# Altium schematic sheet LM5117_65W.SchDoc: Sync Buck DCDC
size 431 x 279 mm; Engineer: Yutao Wang (Steven); Organization: TESLA Motors, INC; Address1: 3500 Deer Creek Road; Address2: Palo Alto, CA; Address4: U.S.A.; SheetNumber: 6; SheetTotal: 7
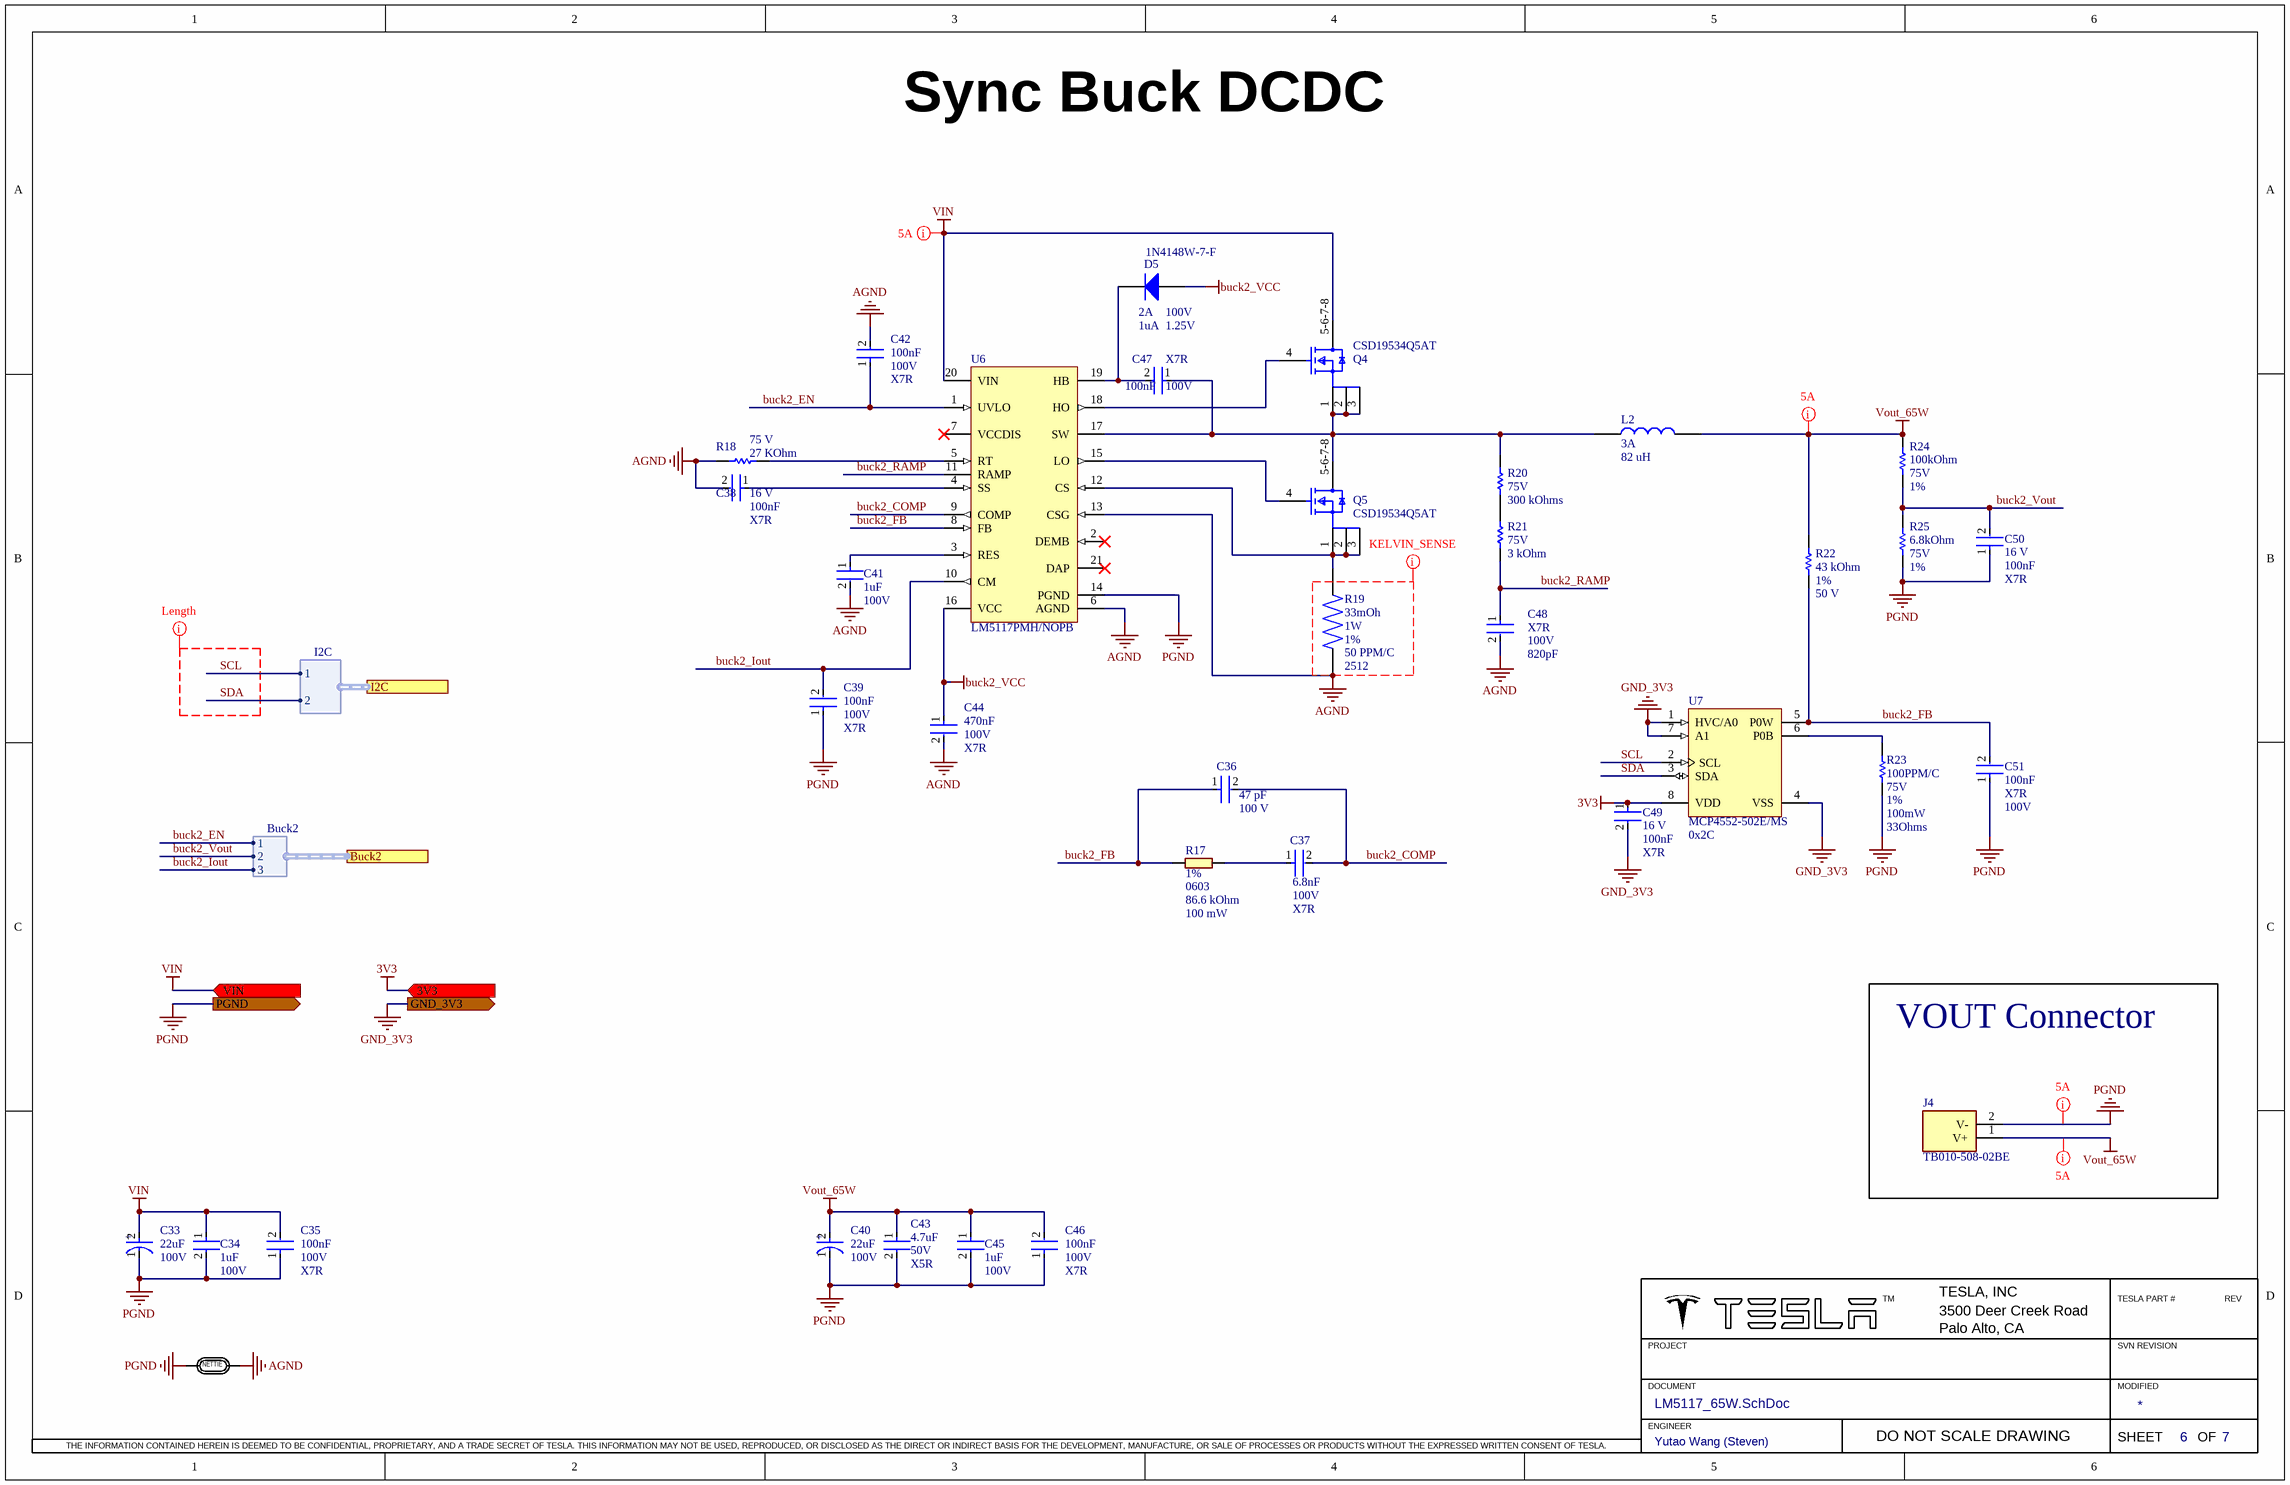
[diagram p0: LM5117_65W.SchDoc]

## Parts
C33  Capacitance: 22uF  Voltage Rating (DC): 100V  [FP-TGF-MFG]  (hidden comment: EEE-TG2A220UP)
C34  Capacitance: 1uF  Voltage: 100V  [FP-C2012-125-0_2-IPC_A]  (hidden comment: C2012X7S2A105K125AB)
C35  Capacitance: 100nF  Dielectric: X7R  Voltage Rating (DC): 100V  [FP-CC1206-0_3-1_45-IPC_C]  (hidden comment: CC1206KKX7R0BB104)
C36  Capacitance: 47 pF  Voltage Rating: 100 V  [FP-C0603C-CF-MFG]  (hidden comment: C0603C470J1GACTU)
C37  Voltage Rating: 100V  Capacitance: 6.8nF  Dielectric: X7R  [FP-GCM188-0_1-IPC_C]  (hidden comment: GCM188R72A682KA37D)
C38  Voltage Rating: 16 V  Capacitance: 100nF  Temperature Characteristic: X7R  [FP-C0402-BB-MFG]  (hidden comment: C0402C104K4RACTU)
C39  Capacitance: 100nF  Dielectric: X7R  Voltage Rating (DC): 100V  [FP-CC1206-0_3-1_45-IPC_C]  (hidden comment: CC1206KKX7R0BB104)
C40  Capacitance: 22uF  Voltage Rating (DC): 100V  [FP-TGF-MFG]  (hidden comment: EEE-TG2A220UP)
C41  Capacitance: 1uF  Voltage: 100V  [FP-C2012-125-0_2-IPC_A]  (hidden comment: C2012X7S2A105K125AB)
C42  Capacitance: 100nF  Dielectric: X7R  Voltage Rating (DC): 100V  [FP-CC1206-0_3-1_45-IPC_C]  (hidden comment: CC1206KKX7R0BB104)
C43  Voltage Rating (DC): 50V  Capacitance: 4.7uF  Dielectric: X5R  [FP-GRM21B-0_15-IPC_C]  (hidden comment: GRM21BR61H475ME51L)
C44  Capacitance: 470nF  Voltage Rating (DC): 100V  Dielectric: X7R  [FP-GRM21B-0_15-IPC_A]  (hidden comment: GRM21BR72A474MA73L)
C45  Capacitance: 1uF  Voltage: 100V  [FP-C2012-125-0_2-IPC_A]  (hidden comment: C2012X7S2A105K125AB)
C46  Capacitance: 100nF  Dielectric: X7R  Voltage Rating (DC): 100V  [FP-CC1206-0_3-1_45-IPC_C]  (hidden comment: CC1206KKX7R0BB104)
C47  Capacitance: 100nF  Dielectric: X7R  Voltage Rating (DC): 100V  [FP-CC1206-0_3-1_45-IPC_C]  (hidden comment: CC1206KKX7R0BB104)
C48  Capacitance: 820pF  Voltage: 100V  Grade: X7R  [FP-GCM155-0_05-IPC_A]  (hidden comment: GCM155R72A821KA37J)
C49  Voltage Rating: 16 V  Capacitance: 100nF  Temperature Characteristic: X7R  [FP-C0402-BB-MFG]  (hidden comment: C0402C104K4RACTU)
C50  Voltage Rating: 16 V  Capacitance: 100nF  Temperature Characteristic: X7R  [FP-C0402-BB-MFG]  (hidden comment: C0402C104K4RACTU)
C51  Capacitance: 100nF  Dielectric: X7R  Voltage Rating (DC): 100V  [FP-CC1206-0_3-1_45-IPC_C]  (hidden comment: CC1206KKX7R0BB104)
D5  1N4148W-7-F  Max Surge Current: 2A  Peak Reverse Voltage: 100V  Ir - Reverse Current: 1uA  Vf - Forward Voltage: 1.25V  [DIOD-SOD123-2_V]
J4  TB010-508-02BE  [CUI_TB010-508-02BE]
L2  Max DC Current: 3A  Inductance: 82 uH  [IHLP5050EZER820M5A]  (hidden comment: IHLP5050EZER820M5A)
NT4  BOARD FEATURE  [NETTIE-0.5X0.5X0.4]  (value not drawn)  (net tie, no BOM)
Q4  CSD19534Q5AT  [FP-DQJ0008A-MFG]
Q5  CSD19534Q5AT  [FP-DQJ0008A-MFG]
R17  value 86.6 kOhm  Tolerence: 1%  Size: 0603  Power: 100 mW  [PE1206FRM470R02L]  (hidden comment: RC0603FR-0786K6L)
R18  Resistance: 27 KOhm  Voltage: 75 V  [RESC1608X55X25LL10T15]  (hidden comment: RC0603FR-0715KL)
R19  value 33mOh  Power: 1W  Tolerence: 1%  PPM: 50 PPM/C  Size: 2512  [PE2512FKE070R033L]  (hidden comment: PE2512FKE070R033L)
R20  Voltage: 75V  Resistance: 300 kOhms  [RESC1608X55X25ML10T15]  (hidden comment: RC0603FR-10300KL)
R21  Voltage: 75V  Resistance: 3 kOhm  [RESC1608X55X25ML10T15]  (hidden comment: RC0603FR-103KL)
R22  Resistance: 43 kOhm  Tolerence: 1%  Voltage: 50 V  [RESC1005X40X25NL05T10]  (hidden comment: RC0402FR-0743KL)
R23  Temperature Coefficient: 100PPM/C  Voltage Rating: 75V  Tolerance: 1%  Power Rating: 100mW  Resistance: 33Ohms  [RESC1608X55X25LL10T15]  (hidden comment: RC0603FR-0733RL)
R24  Resistance: 100kOhm  Voltage: 75V  Tolerence: 1%  [RESC1608X55X30ML15T15]  (hidden comment: ERJ-3EKF1003V)
R25  Voltage: 75V  Resistance: 6.8kOhm  Tolerence: 1%  [RESC1609X55X30NL15T15]  (hidden comment: ERJ-3EKF6801V)
U6  LM5117PMH/NOPB  [PWP0020A_N]
U7  MCP4552-502E/MS  [MSOP-MS8_N]

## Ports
3V3 (in), Buck2 (harness Buck2), GND_3V3 (out), I2C (harness I2C), PGND (out), VIN (in)

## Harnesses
I2C: 1, 2
Buck2: 1, 3, 2

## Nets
3V3: C49.1 U7.8(VDD) ; port 3V3
AGND: C38.2 C41.2 C42.2 C44.2 C48.2 NT4.1(C1) R18.1 R19.1 U6.6(AGND) U6.13(CSG)
buck2_VCC: C44.1 D5.1(A) U6.16(VCC)
GND_3V3: C49.2 U7.1(HVC/A0) U7.4(VSS) U7.7(A1) ; port GND_3V3
PGND: C33.1(C) C34.2 C35.1 C39.1 C40.1(C) C43.2 C45.2 C46.1 C50.1 C51.1 J4.2(V-) NT4.2(C2) R23.2 R25.1 U6.14(PGND) ; port PGND
VIN: C33.2(A) C34.1 C35.2 Q4.5-6-7-8(D) U6.20(VIN) ; port VIN
Vout_65W: C40.2(A) C43.1 C45.1 C46.2 J4.1(V+) L2.2 R22.2 R24.2
buck2_COMP: C36.2 C37.2 U6.9(COMP)
buck2_EN: C42.1 U6.1(UVLO) ; port Buck2.1
buck2_FB: C36.1 C51.2 R17.1 R22.1 U6.8(FB) U7.5(P0W)
buck2_Iout: C39.2 U6.10(CM) ; port Buck2.3
buck2_RAMP: C48.1 R21.1 U6.11(RAMP)
buck2_Vout: C50.2 R24.1 R25.2 ; port Buck2.2
SCL: U7.2(SCL) ; port I2C.1
SDA: U7.3(SDA) ; port I2C.2
NetC37_1: C37.1 R17.2
NetC38_1: C38.1 U6.4(SS)
NetC41_1: C41.1 U6.3(RES)
NetC47_1: C47.1 L2.1 Q4.1(S) Q4.2(S) Q4.3(S) Q5.5-6-7-8(D) R20.2 U6.17(SW)
NetC47_2: C47.2 D5.2(K) U6.19(HB)
NetQ4_4: Q4.4(G) U6.18(HO)
NetQ5_1: Q5.1(S) Q5.2(S) Q5.3(S) R19.2 U6.12(CS)
NetQ5_4: Q5.4(G) U6.15(LO)
NetR18_2: R18.2 U6.5(RT)
NetR20_1: R20.1 R21.2
NetR23_1: R23.1 U7.6(P0B)

Not connected (* = marked no-connect by the designer): U6 2(DEMB)* 7(VCCDIS)* 21(DAP)*

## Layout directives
mark named 5A: PGND, VIN, Vout_65W
net class Length: (no net found under the mark)
mark named KELVIN_SENSE: AGND

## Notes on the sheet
- (near U7) 0x2C
- VOUT Connector

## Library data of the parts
C33 C40 = CMP-05427-002105-1: CAP ALUM 22UF 20% 100V SMD; Dissipation Factor: 0.1%; ESR (Equivalent Series Resistance): 1.3R; Ripple Current: 70mA; Life (Hours): 2000Hour
C34 C41 C45 = CMP-2000-05454-2: Multilayer Ceramic Capacitors 1μF ±10% 100V X7S SMD 0805
C35 C39 C42 C46 C47 C51 = CMP-03422-001499-1: CAP CER 0.1UF 100V X7R 1206; Dielectric Material: Ceramic; Tolerance: 10%
C36 = CMP-2006-03321-2: CAP CER 47PF 100V 5% NP0 0603; Manufacturer: KEMET; Temperature Characteristic: C0G; Temperature Coefficient: 30ppm/°C; Automotive Grade: Grade 1; Material: Ceramic; Tolerance: 0.05
C37 = CMP-2006-02398-2: Ceramic Capacitor for Automotive 6.8nF  ±10% 100VDC X7R 0603 Paper T/R
C38 C49 C50 = CMP-2008-02108-2: CAP CER 0.1UF 16V X7R 0402; Manufacturer: Kemet; Value: 0.10 μF; Tolerance: 0.1; Material: Ceramic; Temperature Coefficient: 15%
C43 = CMP-06035-037765-1: Chip Multilayer Ceramic Capacitors for General Purpose, 0805, 4.7uF, X5R, 15%, 20%, 50V
C44 = CMP-06035-021373-1: Chip Multilayer Ceramic Capacitors for General Purpose, 0805, 0.47uF, X7R, 15%, 20%, 100V
C48 = CMP-06035-060413-1: Ceramic Capacitor for Automotive 820pF ±10% 100VDC X7R 0402 Paper T/R
D5 = CMP-2000-04932-2: Fast Switching Diode, 100 V, 0.15 A, -65 to 150 degC, 2-Pin?SOD123, RoHS, Tape and Reel; Recovery Time: 4ns; Brand: DiodesIncorporated; Unit Weight: 0.000353oz; Configuration: Single; If - Forward Current: 0.15A
J4 = TB010-508-02BE: 2~24 Poles, Screw Type, Horizontal, 5.08 Pitch, 26~12 (AWG), Terminal Block Connector; MF: CUI Devices
L2 = IHLP5050EZER820M5A: Fixed Inductors 82uH 20% High Temp AEC-Q200; Manufacturer_Name: Vishay; Geometry.Height: 5mm; Max Saturation Current: 3.1A; Max DC resistance: 201 mOhms
NT4 = CMP-01115-6: NET TIE 0.5 x 0.5 mm, 0.4mm GAP; Manufacturer PartNo: NONE - BOARD FEATURE; Manufacturer: TESLA; AEC-Q: YES; Level: 1; Selective Soldering: NO; Pressfit: NO; Layout Notes: NET TIE
Q4 Q5 = CMP-04962-000018-1: MOSFET N-CH 100V 50 8SON; Manufacturer: Texas Instruments; Reverse Recovery Time: 53ns; Turn Off Delay Time: 20ns; Gate To Source Voltage: 20V; Turn On Delay Time: 9ns; Depletion Mode: False; Threshold Vgs Max: 3.4V; Pulse Drain Current: 137A; Number Of N Channels: 1; Input Capacitace At Vds: 1290pF @ 50V; Max Junction Temp: +150°C; Power Dissipation: 3.2W; Max Forward Diode Voltage: 1V; Continuous Drain Current: 10A; Drain To Source Resistance: 12.6mΩ; Threshold Vgs Min: 2.4V; Transconductance: 47S; Gate Charge At Vgs: 17nC @ 10V; Reverse Recovery Charge: 134nC; Typ Forward Diode Voltage: 0.8V; Rthja Max: 50°C/W
R17 = RC0603FR-0786K6L: SMD 86.6 kOhms 100 mW 0603 1%
R18 = CMP-1659-00032-1: Chip Resistor, 15 KOhm, +/- 1%, 0.1 W, -55 to 155 degC, 0603 (1608 Metric), RoHS, Tape and Reel
R19 = PE2512FKE070R033L: SMD 33 mOhms 1 Watts 1 % 50 ppm/C
R20 = CMP-2000-04314-1: Thick Film Resistors - SMD 300kOhms 1/10W 0603 1%; Manufacturer: Yageo; Power: 100 mW; PPM: 100 PPM/C
R21 = CMP-2000-04314-1: Thick Film Resistors - SMD 3 kOhms 100 mW 0603 1%; Manufacturer: Yageo
R22 = CMP-1011-00694-2: Thick Film Resistors - SMD 43 kOhms 62.5mW 0402 1%; Manufacturer: Yageo / Phycomp
R23 = CMP-2000-06939-1: Chip Resistor, 33 Ohm, +/- 1%, 0.1 W, -55 to 155 degC, 0603 (1608 Metric), RoHS, Tape and Reel; Unit Weight: 0.000071oz; Brand: Yageo
R24 = CMP-2000-00182-1: Thick Film Resistors - SMD 0603 100Kohms 1% AEC-Q200; Manufacturer: Panasonic
R25 = CMP-1012-00604-3: Chip Resistor, 6.8 KOhm, +/- 1%, 0.1 W, -55 to 155 degC, 0603 (1608 Metric), RoHS, Tape and Reel; Manufacturer PartNo: ERJ-3EKF6800V
U6 = CMP-0069-02227-2: Wide Input Range Synchronous Buck Controller with Analog Current Monitor, 20-pin TSSOP-EP, 73 Rail; Manufacturer: Texas Instruments; CompType: Switcher; High-Reliability: Y; PackageTopMarking: NSUZXYTT*LM5117*PMH
U7 = CMP-0188-00827-2: 8-Bit Single I2C Digital POT with Volatile Memory, 8-pin MSOP, Extended Temperature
